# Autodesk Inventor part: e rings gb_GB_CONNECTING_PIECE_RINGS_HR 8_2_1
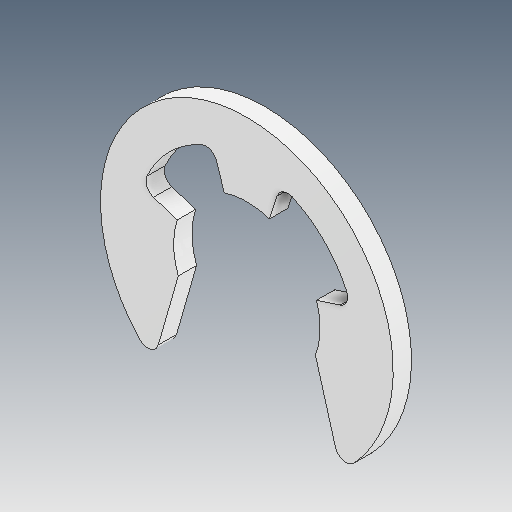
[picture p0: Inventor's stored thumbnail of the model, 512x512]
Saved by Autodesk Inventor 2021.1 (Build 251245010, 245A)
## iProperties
Created: 2021-05
Part Number: e rings gb_GB_CONNECTING_PIECE_RINGS_HR 8_2_1
Material: Ogólny
Document SubType Name: Modeling
Designer: user
Density: 1 g/cm^3
Appearance: Domyślna
Author: user
Revision Number: ÈÎºÎ
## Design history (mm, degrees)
feature "ÊäÈë1"
node "Bryła1"
